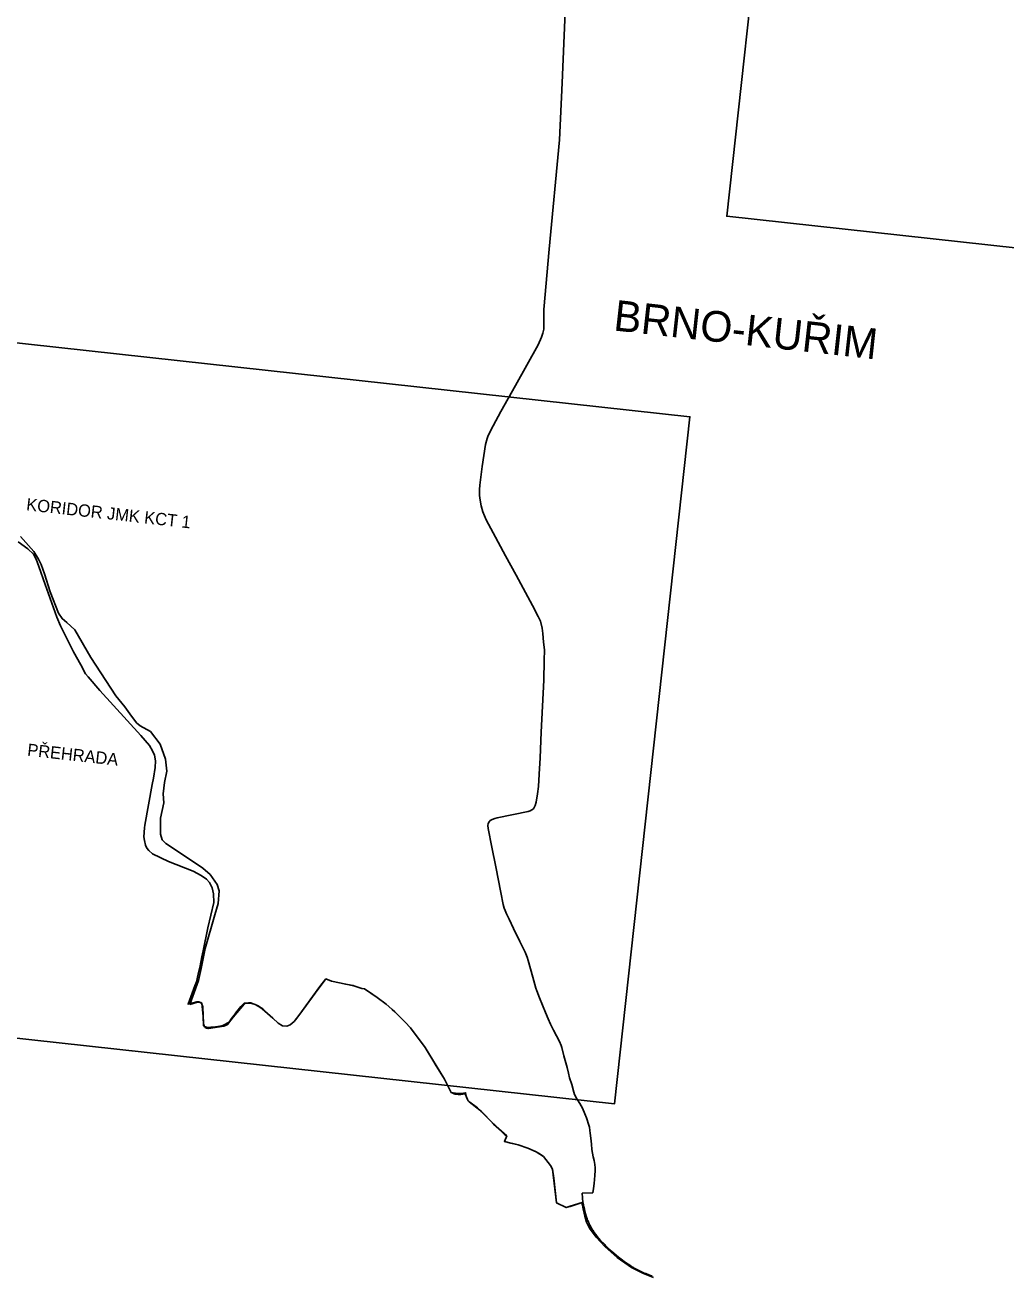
# Model space of a CAD drawing. Extents: x -678204 to -526855, y -1228851 to -1110393.
# Drawn here: x -605756 to -600965, y -1157650 to -1151538 of the extents above; entities that cross this region are included whole.
import ezdxf

# ---------------------------------------------------------------- set-up
doc = ezdxf.new("R2010")
doc.units = 0
for name, color, linetype in [('00_n_cyklo popisy detaily', 7, 'Continuous'), ('00_n_cyklo popisy ostatni', 7, 'Continuous'), ('00_n_cyklo prujezdne rekreacni hlavni', 7, 'Continuous'), ('00_n_cyklo prujezdne rekreacni vedlejsi', 7, 'Continuous'), ('00_n_cyklo studie rekreacni hlavni', 7, 'Continuous'), ('00_n_cyklo studie rekreacni vedlejsi', 7, 'Continuous'), ('00_n_cyklo trasovani rekreacni hlavni', 7, 'Continuous'), ('00_n_cyklo trasovani rekreacni vedlejsi', 7, 'Continuous'), ('_HELP', 7, 'Continuous'), ('trasy_0001', 7, 'Continuous')]:
    doc.layers.add(name, color=color, linetype=linetype)

msp = doc.modelspace()

# ---------------------------------------------------------------- linework, layer by layer
at = {"layer": '00_n_cyklo prujezdne rekreacni hlavni'}
for p, q in [((-604913.7, -1156312.6), (-604951.4, -1156323.3)), ((-604904.7, -1156312.7), (-604905.6, -1156312.5)), ((-604896.4, -1156317.9), (-604898.6, -1156315.9)), ((-604885.1, -1156415.8), (-604887.9, -1156335.8)), ((-604671.3, -1156316.5), (-604683.4, -1156319.3)), ((-604656.3, -1156316.3), (-604669.9, -1156316.3)), ((-604632.1, -1156324), (-604654.5, -1156316.6)), ((-604609.6, -1156336.3), (-604632.1, -1156324)), ((-604597.9, -1156344.9), (-604609.6, -1156336.3)), ((-604881.3, -1156428.5), (-604884.8, -1156417.4)), ((-604864.9, -1156439.8), (-604870.2, -1156438.7)), ((-604827.3, -1156436.4), (-604860.1, -1156440)), ((-603640.5, -1156763), (-603652.1, -1156761.6)), ((-603633.3, -1156763.3), (-603633.6, -1156763.3)), ((-603611, -1156759.7), (-603614.4, -1156760.5)), ((-603595.3, -1156788), (-603605.1, -1156762.7)), ((-603535.4, -1156839.8), (-603587.5, -1156798.5)), ((-603411.9, -1156960.7), (-603522.9, -1156850.8)), ((-603035.7, -1157291.1), (-603093.4, -1157309.5)), ((-603026.4, -1157311.9), (-603029.3, -1157295)), ((-603010.4, -1157370.9), (-603014.9, -1157357.7)), ((-603000.1, -1157396), (-603001.4, -1157393.3)), ((-602987.1, -1157419.8), (-602997.2, -1157401.6)), ((-602891.9, -1157528.4), (-602915.5, -1157506.4)), ((-602867.6, -1157549.7), (-602891.9, -1157528.4)), ((-602851.4, -1157563.3), (-602867.6, -1157549.7)), ((-602823.7, -1157583.6), (-602851.4, -1157563.3)), ((-602797.4, -1157601.1), (-602823.7, -1157583.6)), ((-602755.1, -1157624.7), (-602780.6, -1157611.1)), ((-602738.4, -1157632.5), (-602755.1, -1157624.7)), ((-602706.2, -1157645.5), (-602724.7, -1157638.4))]:
    msp.add_line(p, q, dxfattribs=at)
for points in [[(-604597.9, -1156344.9), (-604545.7, -1156390.6), (-604520.5, -1156414.1), (-604498.7, -1156427.1), (-604478.2, -1156429.7), (-604461.4, -1156422.5), (-604441.7, -1156407), (-604414.2, -1156370.9), (-604339.7, -1156267.8), (-604286.3, -1156198.3), (-604259.9, -1156208.9), (-604190, -1156224.6), (-604154.3, -1156231.1), (-604149.5, -1156232.2), (-604121.4, -1156242.4), (-604111.7, -1156245.3), (-604098.9, -1156246.3), (-604037, -1156289.3), (-603992.2, -1156322.2), (-603949.6, -1156360.1), (-603900.2, -1156409.2), (-603874, -1156438.3), (-603801.4, -1156534), (-603708.1, -1156688.2), (-603675.5, -1156754), (-603667, -1156756.6)], [(-604686.7, -1156321.4), (-604738.9, -1156385.7), (-604766.6, -1156420.6)], [(-604769.1, -1156422.5), (-604785.8, -1156428.9), (-604826.8, -1156436.4)], [(-603411.9, -1156960.7), (-603403.4, -1156966), (-603414.7, -1156992.8), (-603346.8, -1157009.7), (-603300.8, -1157026.1), (-603260.4, -1157042.8), (-603223.4, -1157066.9), (-603189.6, -1157110.5), (-603179.3, -1157127.8), (-603159.6, -1157292.9), (-603113.8, -1157316), (-603093.4, -1157309.5)], [(-602968.8, -1157446.8), (-602976.3, -1157437), (-602981.8, -1157428.2)], [(-602928.1, -1157493.5), (-602944.6, -1157476.7), (-602961.3, -1157456.4)]]:
    msp.add_lwpolyline(points, dxfattribs=at)
for centre, radius, start, end in [((-604909.4, -1156327), 15, 75.43972, 106.93211), ((-604908.5, -1156327.2), 15, 48.81407, 75.43972), ((-604912.9, -1156336.7), 25, 1.97493, 48.81407), ((-604682.1, -1156325.1), 6, 103.09189, 140.94666), ((-604669.9, -1156322.3), 6, 90, 103.09189), ((-604656.3, -1156322.3), 6, 71.7939, 90), ((-604879.1, -1156415.5), 6, 181.97493, 197.59925), ((-604867, -1156424), 15, 197.59925, 257.79953), ((-604861.8, -1156425.1), 15, 257.79953, 276.30161), ((-604827.9, -1156430.5), 6, 276.30161, 280.31815), ((-604771.3, -1156416.9), 6, 290.96851, 321.62591), ((-603647.1, -1156721.9), 40, 240.26856, 262.90384), ((-603635.6, -1156723.3), 40, 262.90143, 272.81598), ((-603638.2, -1156663.4), 100, 272.81551, 283.77891), ((-603609.8, -1156764.5), 5, 21.28605, 103.77733), ((-603572, -1156778.9), 25, 201.28706, 231.64004), ((-603628.4, -1156957.4), 150, 45.3077, 51.64107), ((-603034.2, -1157295.8), 5, 9.59415, 107.65913), ((-602730.6, -1157261.9), 300, 189.59361, 198.61186), ((-602820.9, -1157307.1), 200, 198.6115, 205.5263), ((-602909.8, -1157352.9), 100, 205.52661, 209.12191), ((-602899.7, -1157371.1), 100, 209.12247, 214.81368), ((-602886.7, -1157389.7), 100, 214.81197, 221.81293), ((-602779, -1157360.2), 200, 221.81322, 226.95941), ((-602686.7, -1157434.5), 200, 236.36977, 241.99711), ((-602653, -1157451.7), 200, 244.73223, 249.01211), ((-602634.5, -1157458.8), 200, 249.01346, 252.93153)]:
    msp.add_arc(centre, radius, start, end, dxfattribs=at)
at = {"layer": '00_n_cyklo prujezdne rekreacni vedlejsi'}
msp.add_lwpolyline([(-602982.7, -1157243.6), (-603034.3, -1157245.5), (-603031.6, -1157291.6)], dxfattribs=at)
at = {"layer": '00_n_cyklo studie rekreacni hlavni'}
msp.add_lwpolyline([(-605778.8, -1154036.8), (-605713.2, -1154110), (-605691, -1154147.1), (-605678, -1154173.9), (-605661.5, -1154219.4), (-605633.9, -1154307.6), (-605593.4, -1154411.7), (-605575.4, -1154437.7), (-605551.3, -1154457.8), (-605513.7, -1154493.4), (-605435.1, -1154627.4), (-605312.9, -1154815.5), (-605268.1, -1154869.8), (-605244.2, -1154903.1), (-605211.3, -1154947.7), (-605193.6, -1154962.4), (-605144, -1154989.2), (-605096.6, -1155052.1), (-605069.9, -1155124.6), (-605064.1, -1155182.9), (-605075.6, -1155238.7), (-605081.8, -1155294.5), (-605079, -1155338.7), (-605094.2, -1155412.8), (-605094.8, -1155491.9), (-605086.5, -1155518.4), (-605068.3, -1155537.4), (-604953.4, -1155613.7), (-604888.5, -1155656.9), (-604852.1, -1155688.3), (-604817.4, -1155736.7), (-604807.9, -1155768.5), (-604813.3, -1155829.7), (-604829.9, -1155884.9), (-604875.6, -1156050.2), (-604895.9, -1156147.8), (-604909.1, -1156206.5), (-604951.4, -1156323.3)], dxfattribs=at)
at = {"layer": '00_n_cyklo studie rekreacni vedlejsi'}
for points in [[(-603086.5, -1150877.8), (-603096.6, -1150882.1), (-603117.6, -1151473.5), (-603133.1, -1151820.4), (-603145.6, -1152098)], [(-603145.6, -1152098), (-603196.5, -1152632.6), (-603222.4, -1152928.2), (-603222.4, -1152999.5)], [(-603222.4, -1152999.5), (-603222.4, -1153023.3), (-603226.6, -1153043.5), (-603232.8, -1153062.7), (-603250.1, -1153099.9), (-603360.4, -1153298.4), (-603432.1, -1153425.7), (-603469.6, -1153495.7), (-603493.7, -1153542.8), (-603499.5, -1153557.5), (-603506.3, -1153587.9), (-603522.7, -1153695.3), (-603534, -1153786.4), (-603536.6, -1153807.1), (-603536, -1153836.5), (-603533.8, -1153858.7), (-603528.4, -1153887.6), (-603520.7, -1153917.1), (-603504.3, -1153954.8), (-603469.4, -1154019.5), (-603408.8, -1154132.1), (-603358, -1154225.1), (-603277.8, -1154374.2), (-603249.1, -1154428.4), (-603238.7, -1154451.1), (-603230.7, -1154484.3), (-603227.6, -1154511.2), (-603223.1, -1154552.9), (-603218.8, -1154591.2), (-603219.9, -1154643.1), (-603222.5, -1154738.6), (-603234.4, -1154992.4), (-603240.9, -1155118.8)], [(-603240.9, -1155118.8), (-603245, -1155198), (-603249, -1155258.4), (-603252.7, -1155294.4), (-603259.7, -1155334.7), (-603264.4, -1155351.1), (-603269.3, -1155360.7), (-603273.3, -1155366.7), (-603280.2, -1155373), (-603288.4, -1155377.4), (-603298.3, -1155380.6), (-603450.2, -1155412.2), (-603461.9, -1155415.2), (-603474.5, -1155419.4), (-603483.8, -1155423.9), (-603489.8, -1155430.4), (-603494, -1155439.3), (-603495.6, -1155449.7), (-603494.3, -1155462.8), (-603476, -1155555.6), (-603457.1, -1155651.4), (-603432.3, -1155776.5), (-603420.3, -1155834.2), (-603415.6, -1155852.2), (-603411.7, -1155864.5), (-603404.9, -1155880.9), (-603392.3, -1155906.1), (-603370.2, -1155952), (-603338.8, -1156015.8), (-603325.7, -1156041.6), (-603313.5, -1156067.8), (-603302.8, -1156093), (-603298, -1156107.9), (-603275.5, -1156190), (-603260.7, -1156243.5), (-603256.2, -1156257.4), (-603243.4, -1156290.2), (-603228.6, -1156326.6), (-603214.5, -1156362.9), (-603201.6, -1156394), (-603190.4, -1156419.6), (-603175.5, -1156448.3), (-603145.9, -1156504.5), (-603137.8, -1156523.3), (-603134.8, -1156534.2), (-603124.6, -1156573.7), (-603108.6, -1156631.9), (-603102, -1156659.3), (-603096.1, -1156681.2), (-603085.6, -1156714.7), (-603076, -1156752.3), (-603072.2, -1156763.6), (-603061.3, -1156784.2), (-603047, -1156806.9), (-603032.9, -1156830.7), (-603021.3, -1156857.3), (-603013.6, -1156876.7), (-603011.6, -1156881.9), (-603003.5, -1156907.4), (-602999.9, -1156923.6), (-602997.6, -1156939), (-602996.2, -1156951.6), (-602993.1, -1156975.9), (-602989.8, -1157006), (-602987.5, -1157032.5), (-602980.8, -1157067.6), (-602976.2, -1157086.2), (-602972.6, -1157104.5), (-602971.8, -1157121.9), (-602971.5, -1157134.3), (-602972.5, -1157159.6), (-602976.9, -1157198.1), (-602979.9, -1157222.1), (-602982.7, -1157243.6)]]:
    msp.add_lwpolyline(points, dxfattribs=at)
at = {"layer": '00_n_cyklo trasovani rekreacni hlavni'}
for p, q in [((-604913.7, -1156312.6), (-604951.4, -1156323.3)), ((-604904.7, -1156312.7), (-604905.6, -1156312.5)), ((-604896.4, -1156317.9), (-604898.6, -1156315.9)), ((-604885.1, -1156415.8), (-604887.9, -1156335.8)), ((-604671.3, -1156316.5), (-604683.4, -1156319.3)), ((-604656.3, -1156316.3), (-604669.9, -1156316.3)), ((-604632.1, -1156324), (-604654.5, -1156316.6)), ((-604609.6, -1156336.3), (-604632.1, -1156324)), ((-604597.9, -1156344.9), (-604609.6, -1156336.3)), ((-604881.3, -1156428.5), (-604884.8, -1156417.4)), ((-604864.9, -1156439.8), (-604870.2, -1156438.7)), ((-604827.3, -1156436.4), (-604860.1, -1156440)), ((-603640.5, -1156763), (-603652.1, -1156761.6)), ((-603633.3, -1156763.3), (-603633.6, -1156763.3)), ((-603611, -1156759.7), (-603614.4, -1156760.5)), ((-603595.3, -1156788), (-603605.1, -1156762.7)), ((-603535.4, -1156839.8), (-603587.5, -1156798.5)), ((-603411.9, -1156960.7), (-603522.9, -1156850.8)), ((-603035.7, -1157291.1), (-603093.4, -1157309.5)), ((-603026.4, -1157311.9), (-603029.3, -1157295)), ((-603010.4, -1157370.9), (-603014.9, -1157357.7)), ((-603000.1, -1157396), (-603001.4, -1157393.3)), ((-602987.1, -1157419.8), (-602997.2, -1157401.6)), ((-602891.9, -1157528.4), (-602915.5, -1157506.4)), ((-602867.6, -1157549.7), (-602891.9, -1157528.4)), ((-602851.4, -1157563.3), (-602867.6, -1157549.7)), ((-602823.7, -1157583.6), (-602851.4, -1157563.3)), ((-602797.4, -1157601.1), (-602823.7, -1157583.6)), ((-602755.1, -1157624.7), (-602780.6, -1157611.1)), ((-602738.4, -1157632.5), (-602755.1, -1157624.7)), ((-602706.2, -1157645.5), (-602724.7, -1157638.4))]:
    msp.add_line(p, q, dxfattribs=at)
for points in [[(-605778.8, -1154036.8), (-605713.2, -1154110), (-605691, -1154147.1), (-605678, -1154173.9), (-605661.5, -1154219.4), (-605633.9, -1154307.6), (-605593.4, -1154411.7), (-605575.4, -1154437.7), (-605551.3, -1154457.8), (-605513.7, -1154493.4), (-605435.1, -1154627.4), (-605312.9, -1154815.5), (-605268.1, -1154869.8), (-605244.2, -1154903.1), (-605211.3, -1154947.7), (-605193.6, -1154962.4), (-605144, -1154989.2), (-605096.6, -1155052.1), (-605069.9, -1155124.6), (-605064.1, -1155182.9), (-605075.6, -1155238.7), (-605081.8, -1155294.5), (-605079, -1155338.7), (-605094.2, -1155412.8), (-605094.8, -1155491.9), (-605086.5, -1155518.4), (-605068.3, -1155537.4), (-604953.4, -1155613.7), (-604888.5, -1155656.9), (-604852.1, -1155688.3), (-604817.4, -1155736.7), (-604807.9, -1155768.5), (-604813.3, -1155829.7), (-604829.9, -1155884.9), (-604875.6, -1156050.2), (-604895.9, -1156147.8), (-604909.1, -1156206.5), (-604951.4, -1156323.3)], [(-604597.9, -1156344.9), (-604545.7, -1156390.6), (-604520.5, -1156414.1), (-604498.7, -1156427.1), (-604478.2, -1156429.7), (-604461.4, -1156422.5), (-604441.7, -1156407), (-604414.2, -1156370.9), (-604339.7, -1156267.8), (-604286.3, -1156198.3), (-604259.9, -1156208.9), (-604190, -1156224.6), (-604154.3, -1156231.1), (-604149.5, -1156232.2), (-604121.4, -1156242.4), (-604111.7, -1156245.3), (-604098.9, -1156246.3), (-604037, -1156289.3), (-603992.2, -1156322.2), (-603949.6, -1156360.1), (-603900.2, -1156409.2), (-603874, -1156438.3), (-603801.4, -1156534), (-603708.1, -1156688.2), (-603675.5, -1156754), (-603667, -1156756.6)], [(-604686.7, -1156321.4), (-604738.9, -1156385.7), (-604766.6, -1156420.6)], [(-604769.1, -1156422.5), (-604785.8, -1156428.9), (-604826.8, -1156436.4)], [(-603411.9, -1156960.7), (-603403.4, -1156966), (-603414.7, -1156992.8), (-603346.8, -1157009.7), (-603300.8, -1157026.1), (-603260.4, -1157042.8), (-603223.4, -1157066.9), (-603189.6, -1157110.5), (-603179.3, -1157127.8), (-603159.6, -1157292.9), (-603113.8, -1157316), (-603093.4, -1157309.5)], [(-602968.8, -1157446.8), (-602976.3, -1157437), (-602981.8, -1157428.2)], [(-602928.1, -1157493.5), (-602944.6, -1157476.7), (-602961.3, -1157456.4)]]:
    msp.add_lwpolyline(points, dxfattribs=at)
for centre, radius, start, end in [((-604909.4, -1156327), 15, 75.43972, 106.93211), ((-604908.5, -1156327.2), 15, 48.81407, 75.43972), ((-604912.9, -1156336.7), 25, 1.97493, 48.81407), ((-604682.1, -1156325.1), 6, 103.09189, 140.94666), ((-604669.9, -1156322.3), 6, 90, 103.09189), ((-604656.3, -1156322.3), 6, 71.7939, 90), ((-604879.1, -1156415.5), 6, 181.97493, 197.59925), ((-604867, -1156424), 15, 197.59925, 257.79953), ((-604861.8, -1156425.1), 15, 257.79953, 276.30161), ((-604827.9, -1156430.5), 6, 276.30161, 280.31815), ((-604771.3, -1156416.9), 6, 290.96851, 321.62591), ((-603647.1, -1156721.9), 40, 240.26856, 262.90384), ((-603635.6, -1156723.3), 40, 262.90143, 272.81598), ((-603638.2, -1156663.4), 100, 272.81551, 283.77891), ((-603609.8, -1156764.5), 5, 21.28605, 103.77733), ((-603572, -1156778.9), 25, 201.28706, 231.64004), ((-603628.4, -1156957.4), 150, 45.3077, 51.64107), ((-603034.2, -1157295.8), 5, 9.59415, 107.65913), ((-602730.6, -1157261.9), 300, 189.59361, 198.61186), ((-602820.9, -1157307.1), 200, 198.6115, 205.5263), ((-602909.8, -1157352.9), 100, 205.52661, 209.12191), ((-602899.7, -1157371.1), 100, 209.12247, 214.81368), ((-602886.7, -1157389.7), 100, 214.81197, 221.81293), ((-602779, -1157360.2), 200, 221.81322, 226.95941), ((-602686.7, -1157434.5), 200, 236.36977, 241.99711), ((-602653, -1157451.7), 200, 244.73223, 249.01211), ((-602634.5, -1157458.8), 200, 249.01346, 252.93153)]:
    msp.add_arc(centre, radius, start, end, dxfattribs=at)
at = {"layer": '00_n_cyklo trasovani rekreacni vedlejsi'}
for points in [[(-603086.5, -1150877.8), (-603096.6, -1150882.1), (-603117.6, -1151473.5), (-603133.1, -1151820.4), (-603145.6, -1152098)], [(-603145.6, -1152098), (-603196.5, -1152632.6), (-603222.4, -1152928.2), (-603222.4, -1152999.5)], [(-603222.4, -1152999.5), (-603222.4, -1153023.3), (-603226.6, -1153043.5), (-603232.8, -1153062.7), (-603250.1, -1153099.9), (-603360.4, -1153298.4), (-603432.1, -1153425.7), (-603469.6, -1153495.7), (-603493.7, -1153542.8), (-603499.5, -1153557.5), (-603506.3, -1153587.9), (-603522.7, -1153695.3), (-603534, -1153786.4), (-603536.6, -1153807.1), (-603536, -1153836.5), (-603533.8, -1153858.7), (-603528.4, -1153887.6), (-603520.7, -1153917.1), (-603504.3, -1153954.8), (-603469.4, -1154019.5), (-603408.8, -1154132.1), (-603358, -1154225.1), (-603277.8, -1154374.2), (-603249.1, -1154428.4), (-603238.7, -1154451.1), (-603230.7, -1154484.3), (-603227.6, -1154511.2), (-603223.1, -1154552.9), (-603218.8, -1154591.2), (-603219.9, -1154643.1), (-603222.5, -1154738.6), (-603234.4, -1154992.4), (-603240.9, -1155118.8)], [(-603240.9, -1155118.8), (-603245, -1155198), (-603249, -1155258.4), (-603252.7, -1155294.4), (-603259.7, -1155334.7), (-603264.4, -1155351.1), (-603269.3, -1155360.7), (-603273.3, -1155366.7), (-603280.2, -1155373), (-603288.4, -1155377.4), (-603298.3, -1155380.6), (-603450.2, -1155412.2), (-603461.9, -1155415.2), (-603474.5, -1155419.4), (-603483.8, -1155423.9), (-603489.8, -1155430.4), (-603494, -1155439.3), (-603495.6, -1155449.7), (-603494.3, -1155462.8), (-603476, -1155555.6), (-603457.1, -1155651.4), (-603432.3, -1155776.5), (-603420.3, -1155834.2), (-603415.6, -1155852.2), (-603411.7, -1155864.5), (-603404.9, -1155880.9), (-603392.3, -1155906.1), (-603370.2, -1155952), (-603338.8, -1156015.8), (-603325.7, -1156041.6), (-603313.5, -1156067.8), (-603302.8, -1156093), (-603298, -1156107.9), (-603275.5, -1156190), (-603260.7, -1156243.5), (-603256.2, -1156257.4), (-603243.4, -1156290.2), (-603228.6, -1156326.6), (-603214.5, -1156362.9), (-603201.6, -1156394), (-603190.4, -1156419.6), (-603175.5, -1156448.3), (-603145.9, -1156504.5), (-603137.8, -1156523.3), (-603134.8, -1156534.2), (-603124.6, -1156573.7), (-603108.6, -1156631.9), (-603102, -1156659.3), (-603096.1, -1156681.2), (-603085.6, -1156714.7), (-603076, -1156752.3), (-603072.2, -1156763.6), (-603061.3, -1156784.2), (-603047, -1156806.9), (-603032.9, -1156830.7), (-603021.3, -1156857.3), (-603013.6, -1156876.7), (-603011.6, -1156881.9), (-603003.5, -1156907.4), (-602999.9, -1156923.6), (-602997.6, -1156939), (-602996.2, -1156951.6), (-602993.1, -1156975.9), (-602989.8, -1157006), (-602987.5, -1157032.5), (-602980.8, -1157067.6), (-602976.2, -1157086.2), (-602972.6, -1157104.5), (-602971.8, -1157121.9), (-602971.5, -1157134.3), (-602972.5, -1157159.6), (-602976.9, -1157198.1), (-602979.9, -1157222.1), (-602982.7, -1157243.6)], [(-602982.7, -1157243.6), (-603034.3, -1157245.5), (-603031.6, -1157291.6)]]:
    msp.add_lwpolyline(points, dxfattribs=at)
at = {"layer": '_HELP'}
for points in [[(-601960.4, -1149114.5), (-597245.8, -1149632.2), (-597614.5, -1152989.7), (-602329, -1152472)], [(-607223.1, -1152933.9), (-602508.5, -1153451.6), (-602877.2, -1156809.1), (-607591.8, -1156291.4)]]:
    msp.add_lwpolyline(points, close=True, dxfattribs=at)
at = {"layer": 'trasy_0001'}
msp.add_lwpolyline([(-602686.8, -1157657.8), (-602735.5, -1157637.3), (-602793.2, -1157607.8), (-602864.5, -1157559.6), (-602922.7, -1157506.9), (-602965.9, -1157460.5), (-602998.7, -1157415.8), (-603013.9, -1157386.8), (-603021.8, -1157358.2), (-603030.4, -1157321.4), (-603033.6, -1157304.6), (-603036.3, -1157291.8), (-603050.4, -1157296.2), (-603093.5, -1157309.7), (-603113.8, -1157316), (-603159.6, -1157292.9), (-603173.6, -1157172.3), (-603179.3, -1157127.8), (-603189.6, -1157110.5), (-603223.4, -1157066.9), (-603239.8, -1157055), (-603260.4, -1157042.8), (-603263.1, -1157041.7), (-603300.8, -1157026.1), (-603346.8, -1157009.7), (-603383.6, -1157000.6), (-603414.7, -1156992.8), (-603403.4, -1156966), (-603467.4, -1156908.5), (-603481.4, -1156894), (-603517.5, -1156855.9), (-603528.2, -1156844), (-603546.8, -1156827.9), (-603583.5, -1156801.3), (-603593, -1156791.2), (-603599.6, -1156777.7), (-603604.1, -1156755), (-603624.7, -1156758), (-603644.3, -1156758), (-603675.5, -1156754), (-603708.1, -1156688.2), (-603755.6, -1156609.8), (-603759.7, -1156603), (-603801.4, -1156534), (-603874, -1156438.3), (-603900.2, -1156409.2), (-603917.8, -1156392.6), (-603924.3, -1156386), (-603943.4, -1156366.4), (-603949.6, -1156360.1), (-603963.8, -1156347.6), (-603992.2, -1156322.2), (-604037, -1156289.3), (-604057.6, -1156274.2), (-604098.9, -1156246.3), (-604111.7, -1156245.3), (-604121.4, -1156242.4), (-604149.5, -1156232.2), (-604159, -1156229.9), (-604190, -1156224.6), (-604259.9, -1156208.9), (-604286.3, -1156198.3), (-604316.2, -1156235.3), (-604363.2, -1156300.2), (-604414.2, -1156370.9), (-604429, -1156390.3), (-604441.7, -1156407), (-604461.4, -1156422.5), (-604478.2, -1156429.7), (-604498.7, -1156427.1), (-604520.5, -1156414.1), (-604545.7, -1156390.6), (-604582.2, -1156357.1), (-604594.4, -1156344.9), (-604603.2, -1156339), (-604620.8, -1156328.6), (-604653.1, -1156315.1), (-604665.3, -1156316), (-604685.4, -1156317.2), (-604702.2, -1156332.8), (-604728.1, -1156366.6), (-604728.2, -1156366.7), (-604747.5, -1156391.5), (-604759.2, -1156409.9), (-604790.2, -1156425.6), (-604805.2, -1156429.3), (-604835.7, -1156434.9), (-604849, -1156435), (-604863.7, -1156436.1), (-604880.6, -1156431.5), (-604885.2, -1156427), (-604885.9, -1156382.2), (-604890.8, -1156333.1), (-604892.7, -1156319.3), (-604896.7, -1156314.5), (-604899.5, -1156313.5), (-604907.8, -1156310.5), (-604916.8, -1156310.5), (-604959.9, -1156322.3), (-604926.5, -1156232.1), (-604919.2, -1156212.5), (-604910, -1156175), (-604901.3, -1156135.3), (-604892, -1156090.4), (-604886, -1156061.9), (-604862.6, -1155949.6), (-604833.8, -1155825.8), (-604835.9, -1155782.9), (-604841.7, -1155753.6), (-604856, -1155728.2), (-604870.4, -1155711.9), (-604895.7, -1155692.6), (-604934.6, -1155672.2), (-605055.3, -1155624.1), (-605133.6, -1155587.9), (-605152.2, -1155571.3), (-605162, -1155560.3), (-605167.6, -1155545.6), (-605173.1, -1155522.4), (-605175.7, -1155504.5), (-605173.2, -1155459.9), (-605171.2, -1155447.1), (-605134.6, -1155248.1), (-605129.4, -1155218.3), (-605120.7, -1155165.2), (-605119.3, -1155133.7), (-605124.4, -1155105.9), (-605133.6, -1155084.6), (-605148.9, -1155058.2), (-605190.2, -1155009), (-605391.6, -1154789.7), (-605448.5, -1154723), (-605460.6, -1154707.3), (-605483.9, -1154663.7), (-605520.3, -1154599.8), (-605583.7, -1154473.4), (-605601.5, -1154431.6), (-605657.9, -1154270.8), (-605688.4, -1154183.9), (-605702.2, -1154147.5), (-605715.7, -1154122.9), (-605743, -1154097.5), (-605789.8, -1154063.7)], dxfattribs=at)

# ---------------------------------------------------------------- texts
at = {"layer": '00_n_cyklo popisy detaily'}
for s, p in [('KORIDOR JMK KCT 1', (-605752.5, -1153908.6)), ('PŘEHRADA', (-605747.5, -1155107.8))]:
    msp.add_text(s, height=60, rotation=353.68355, dxfattribs=at).set_placement(p)
at = {"layer": '00_n_cyklo popisy ostatni'}
msp.add_text('BRNO-KUŘIM', height=150, rotation=353.68355, dxfattribs=at).set_placement((-602885.7, -1153029.7))

doc.saveas('drawing.dxf')
